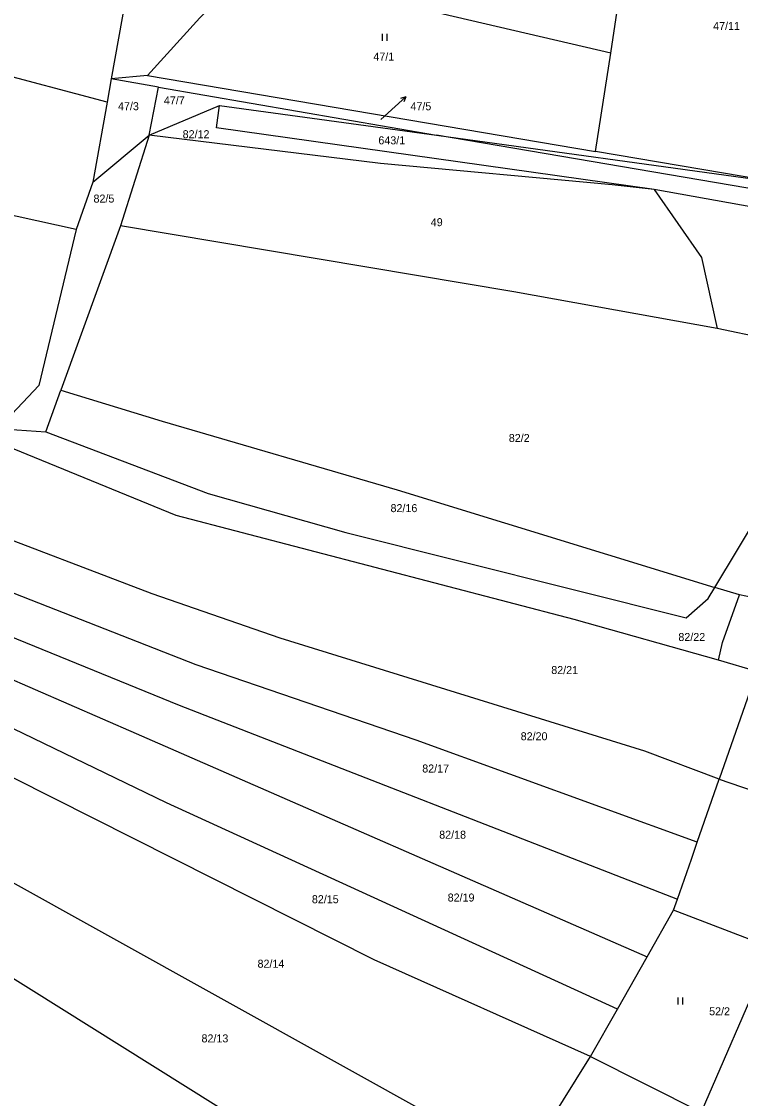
# Model space of a CAD drawing. Extents: x -746176 to -739709, y -1128407 to -1124482.
# Drawn here: x -743188.7 to -743036.1, y -1127574.6 to -1127345.9 of the extents above; entities that cross this region are included whole.
import ezdxf

# ---------------------------------------------------------------- set-up
doc = ezdxf.new("R2010")
doc.units = 0
for name, color, linetype in [('Vrstva 33', 7, 'Continuous'), ('Vrstva 42', 7, 'Continuous'), ('Vrstva 43', 7, 'Continuous'), ('Vrstva 44', 7, 'Continuous')]:
    doc.layers.add(name, color=color, linetype=linetype)

msp = doc.modelspace()

# ---------------------------------------------------------------- linework, layer by layer
at = {"layer": 'Vrstva 33'}
for p, q in [((-743163.52, -1127323.93), (-743169.65, -1127358.07)), ((-743063.68, -1127352.59), (-743059.46, -1127325.17)), ((-743063.68, -1127352.59), (-743140.7, -1127334.62)), ((-743066.9, -1127373.47), (-743063.68, -1127352.59)), ((-743169.65, -1127358.07), (-743170.53, -1127362.98)), ((-743161.95, -1127357.36), (-743169.65, -1127358.07)), ((-743159.66, -1127359.81), (-743169.65, -1127358.07)), ((-743161.95, -1127357.36), (-743066.9, -1127373.47)), ((-743161.61, -1127370.05), (-743159.66, -1127359.81)), ((-743159.66, -1127359.81), (-743100.68, -1127370.05)), ((-743170.53, -1127362.98), (-743173.59, -1127379.99)), ((-743161.61, -1127370.05), (-743146.67, -1127363.71)), ((-743146.67, -1127363.71), (-743100.68, -1127370.05)), ((-743173.59, -1127379.99), (-743161.61, -1127370.05)), ((-743161.61, -1127370.05), (-743167.67, -1127389.27)), ((-743100.68, -1127370.05), (-743028.55, -1127379.99)), ((-743028.55, -1127379.99), (-743066.9, -1127373.47)), ((-743173.59, -1127379.99), (-743177.11, -1127390.05)), ((-743177.11, -1127390.05), (-743199.65, -1127385.13)), ((-743167.67, -1127389.27), (-743180.36, -1127424.17)), ((-743009.13, -1127417.82), (-743041.1, -1127411.11)), ((-743183.58, -1127433.05), (-743180.36, -1127424.17)), ((-743202.45, -1127431.75), (-743183.58, -1127433.05)), ((-743036.38, -1127467.62), (-743041.59, -1127466.09)), ((-743027.39, -1127469.59), (-743036.38, -1127467.62)), ((-743032.69, -1127483.96), (-743040.81, -1127481.55)), ((-743032.69, -1127483.96), (-743040.66, -1127506.77)), ((-743082.43, -1127588.87), (-743239.89, -1127501.37)), ((-743045.31, -1127520.19), (-743040.66, -1127506.77)), ((-743040.66, -1127506.77), (-743018.83, -1127514.29)), ((-743050.32, -1127534.62), (-743049.5, -1127532.27)), ((-743055.93, -1127544.5), (-743050.32, -1127534.62)), ((-743029.41, -1127542.64), (-743050.32, -1127534.62)), ((-743029.41, -1127542.64), (-743044.5, -1127577.53)), ((-743062.27, -1127555.66), (-743055.93, -1127544.5)), ((-743067.95, -1127565.66), (-743062.27, -1127555.66)), ((-743082.43, -1127588.87), (-743067.95, -1127565.66)), ((-743067.95, -1127565.66), (-743044.5, -1127577.53))]:
    msp.add_line(p, q, dxfattribs=at)
for points in [[(-743170.53, -1127362.98), (-743196.16, -1127356.25), (-743296.23, -1127335.74)], [(-743140.7, -1127334.62), (-743150.85, -1127345.11), (-743161.95, -1127357.36)], [(-743054.48, -1127381.54), (-743147.34, -1127368.46), (-743146.67, -1127363.71)], [(-743054.48, -1127381.54), (-743063.36, -1127380.56), (-743112.56, -1127376.02), (-743161.61, -1127370.05)], [(-742967.2, -1127394.53), (-742996.94, -1127389.89), (-743028.35, -1127382.31), (-743100.68, -1127370.05)], [(-743021.3, -1127386.55), (-743030.41, -1127385.86), (-743054.48, -1127381.54)], [(-743054.48, -1127381.54), (-743044.4, -1127395.97), (-743041.1, -1127411.11)], [(-743177.11, -1127390.05), (-743185.02, -1127423.21), (-743191.91, -1127430.5), (-743207.37, -1127426.59)], [(-743041.1, -1127411.11), (-743084.2, -1127403.32), (-743167.67, -1127389.27)], [(-743180.36, -1127424.17), (-743158.88, -1127430.74), (-743108.99, -1127445.38), (-743041.59, -1127466.09)], [(-743040.81, -1127481.55), (-743071.4, -1127472.85), (-743155.92, -1127450.8), (-743202.45, -1127431.75)], [(-743183.58, -1127433.05), (-743149.11, -1127446.12), (-743119.92, -1127454.41), (-743047.66, -1127472.53), (-743042.97, -1127468.39), (-743041.59, -1127466.09)], [(-743041.59, -1127466.09), (-743027.12, -1127442.06), (-743016.5, -1127438.72)], [(-743040.66, -1127506.77), (-743056.44, -1127500.82), (-743133.85, -1127476.88), (-743160.99, -1127467.42), (-743199.57, -1127452.71), (-743214.09, -1127445.46)], [(-743045.31, -1127520.19), (-743104.96, -1127498.48), (-743151.66, -1127482.51), (-743195.56, -1127465.33), (-743218.68, -1127453.92)], [(-743221.96, -1127460.98), (-743195.25, -1127474.76), (-743155.28, -1127491.09), (-743049.5, -1127532.27)], [(-743225.6, -1127468.62), (-743200.19, -1127481.49), (-743164.36, -1127497.11), (-743055.93, -1127544.5)], [(-743040.81, -1127481.55), (-743039.98, -1127477.77), (-743036.38, -1127467.62)], [(-743062.27, -1127555.66), (-743157.93, -1127511.82), (-743229.49, -1127477.19)], [(-743067.95, -1127565.66), (-743113.85, -1127545.15), (-743233.06, -1127485.07)], [(-743096.19, -1127609.82), (-743127.6, -1127588.59), (-743246.36, -1127514.17)], [(-743049.5, -1127532.27), (-743046.55, -1127523.76), (-743045.31, -1127520.19)]]:
    msp.add_lwpolyline(points, dxfattribs=at)
at = {"layer": 'Vrstva 43'}
for p, q in [((-743109.4, -1127363.92), (-743107.17, -1127361.91)), ((-743107.17, -1127361.91), (-743108.25, -1127362.21)), ((-743107.17, -1127361.91), (-743107.58, -1127362.95)), ((-743112.48, -1127366.7), (-743109.4, -1127363.92))]:
    msp.add_line(p, q, dxfattribs=at)
at = {"layer": 'Vrstva 44'}
for p, q in [((-743112.08, -1127349.98), (-743112.08, -1127348.48)), ((-743111.08, -1127349.98), (-743111.08, -1127348.48)), ((-743049.37, -1127554.65), (-743049.37, -1127553.15)), ((-743048.37, -1127554.65), (-743048.37, -1127553.15))]:
    msp.add_line(p, q, dxfattribs=at)

# ---------------------------------------------------------------- texts
at = {"layer": 'Vrstva 42'}
for s, p in [('47/11', (-743041.94, -1127347.69)), ('47/1', (-743114.04, -1127354.19)), ('47/3', (-743168.23, -1127364.72)), ('47/7', (-743158.5, -1127363.48)), ('47/5', (-743106.17, -1127364.74)), ('82/12', (-743154.51, -1127370.67)), ('643/1', (-743112.98, -1127371.97)), ('82/5', (-743173.43, -1127384.34)), ('49', (-743101.86, -1127389.35)), ('82/2', (-743085.3, -1127435.18)), ('82/16', (-743110.4, -1127450.08)), ('82/22', (-743049.32, -1127477.45)), ('82/21', (-743076.29, -1127484.47)), ('82/20', (-743082.78, -1127498.53)), ('82/17', (-743103.67, -1127505.38)), ('82/18', (-743100.07, -1127519.44)), ('82/15', (-743127.09, -1127533.14)), ('82/19', (-743098.27, -1127532.78)), ('82/14', (-743138.62, -1127546.84)), ('52/2', (-743042.79, -1127556.94)), ('82/13', (-743150.51, -1127562.7))]:
    msp.add_text(s, height=1.7, dxfattribs=at).set_placement(p)

doc.saveas('drawing.dxf')
